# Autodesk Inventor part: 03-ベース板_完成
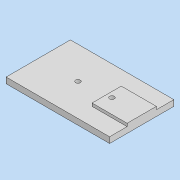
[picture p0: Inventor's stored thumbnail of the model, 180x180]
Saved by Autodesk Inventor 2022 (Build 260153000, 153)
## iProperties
Created: 2021-07
Part Number: 03-ベース板_完成
Material: 一般
Document SubType Name: Modeling
Designer: DesignLab
Density: 1 g/cm^3
Appearance: 既定
Author: DesignLab
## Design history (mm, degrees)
sketch "スケッチ1"
  geometry: L1 (-177, -55)-(0, -55); L2 (0, -55)-(0, 55); L3 (0, 55)-(-177, 55); L4 (-177, 55)-(-177, -55); 2 further points
  constraints: 8 end point, 2 parallel, 1 coincident, 1 horizontal, 1 midpoint, 1 perpendicular
  dimensions: "d0" = 177 distance of L3.end L2.end; "d1" = 110 distance of L2.end L1.end
extrude "押し出し1" new body sketch "スケッチ1" distance "d2" = 10; taper "d3" = 0 deg
sketch "スケッチ2"
  geometry: L1 (-60, -25)-(0, -25); L2 (0, -25)-(0, 25); L3 (0, 25)-(-60, 25); L4 (-60, 25)-(-60, -25); L5 (0, -55)-(0, 55) reference; 2 further points
  constraints: 8 end point, 2 midpoint, 2 parallel, 1 horizontal, 1 perpendicular
  dimensions: "d4" = 60 distance of L3.end L2.end; "d5" = 50 distance of L2.end L1.end
extrude "押し出し2" join sketch "スケッチ2" distance "d6" = 5; taper "d7" = 0 deg
sketch "スケッチ3"
  geometry: L1 (0, 0)-(-51, 0)
  constraints: 2 end point, 1 horizontal
  dimensions: "d8" = 51 distance of L1.start L1.end
hole "穴1" sketch "スケッチ3" at (-51, 0) diameter "d9" = 8; stored, may be unused: countersink angle "d13" = 90 deg, drill point angle "d15" = 118 deg; dims "d10" = 6, "d11" = 4, "d12" = 2, "d14" = 8
pattern_linear "矩形状パターン1" dims "d18" = 58
node "ソリッド1"
